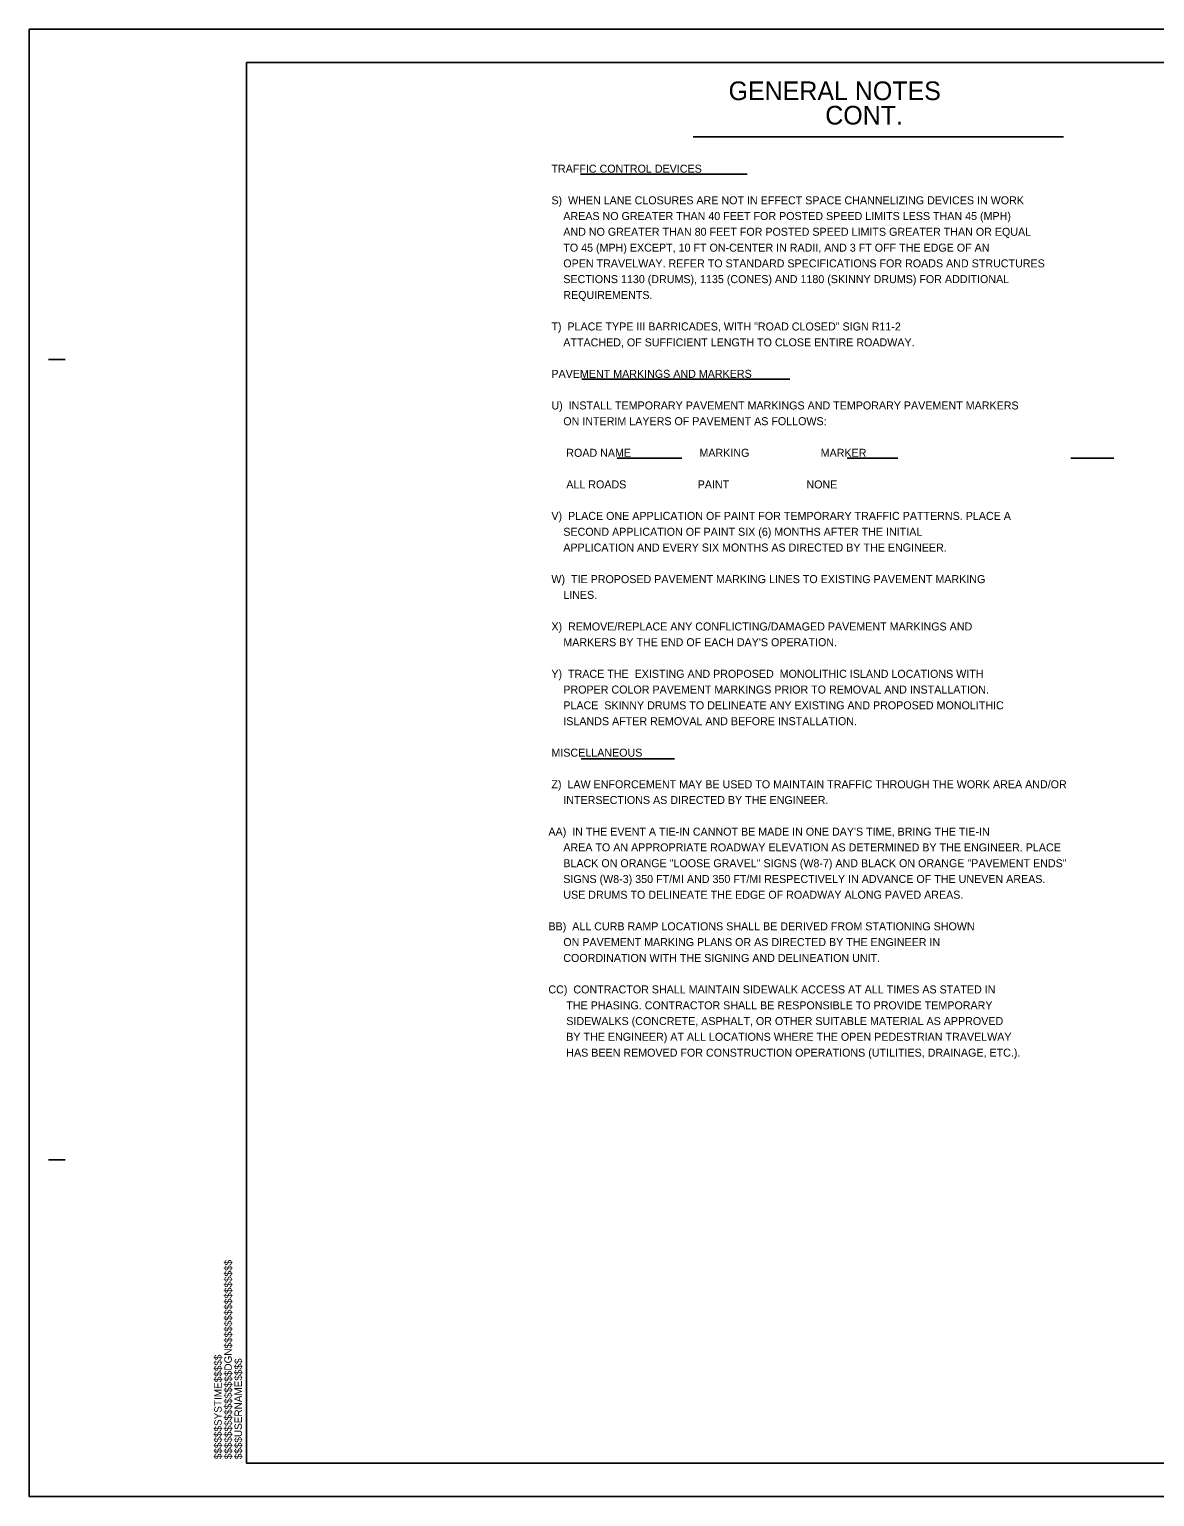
# Model space of a CAD drawing. Extents: x 762655 to 770567, y 650864 to 655190.
# Drawn here: x 764521 to 765365, y 652779 to 653879 of the extents above; entities that cross this region are included whole.
import ezdxf

# ---------------------------------------------------------------- set-up
doc = ezdxf.new("R2010")
doc.units = 0
for name, color, linetype in [('Default', 7, 'Continuous'), ('DEV BORDER CELL', 7, 'Continuous'), ('DEV TRANSPORTATION OPERATIONS PLAN SHEET', 7, 'Continuous'), ('Scratch_Level_3', 7, 'Continuous'), ('Sheet Plot Border Outside CELL', 7, 'Continuous')]:
    doc.layers.add(name, color=color, linetype=linetype)

msp = doc.modelspace()

# ---------------------------------------------------------------- linework, layer by layer
at = {"layer": 'Default'}
for p, q in [((764934.2, 653770.2), (765059.2, 653770.2)), ((764935.2, 653616.4), (765091.2, 653616.4)), ((764961.6, 653557.2), (765010.3, 653557.2)), ((765134.3, 653557.2), (765172.2, 653557.2)), ((765301.9, 653557.2), (765334.3, 653557.2)), ((764934.6, 653332), (765004.7, 653332))]:
    msp.add_line(p, q, dxfattribs=at)
at = {"layer": 'DEV BORDER CELL'}
for p, q in [((764684.8, 653853.8), (764684.8, 653853.8)), ((765018.6, 653798.2), (765296.5, 653798.2)), ((764535.3, 653631.3), (764547.8, 653631.3)), ((764535.3, 653031.3), (764547.8, 653031.3)), ((764683.8, 652803.8), (764683.8, 652803.8))]:
    msp.add_line(p, q, dxfattribs=at)
msp.add_lwpolyline([(766183.8, 653853.8), (764683.8, 653853.8), (764683.8, 652803.8), (766183.8, 652803.8)], close=True, dxfattribs=at)
at = {"layer": 'Scratch_Level_3'}
msp.add_lwpolyline([(764520.8, 653878.8), (766208.8, 653878.8), (766208.8, 652778.8), (764520.8, 652778.8)], close=True, dxfattribs=at)
at = {"layer": 'Sheet Plot Border Outside CELL'}
msp.add_lwpolyline([(764520.8, 652778.8), (766208.8, 652778.8), (766208.8, 653878.8), (764520.8, 653878.8)], close=True, dxfattribs=at)

# ---------------------------------------------------------------- texts
at = {"layer": 'Default'}
for s, p in [('       TRAFFIC CONTROL DEVICES', (764896.8, 653771.3)), ('       S)  WHEN LANE CLOSURES ARE NOT IN EFFECT SPACE CHANNELIZING DEVICES IN WORK', (764896.8, 653747.6)), ('           AREAS NO GREATER THAN 40 FEET FOR POSTED SPEED LIMITS LESS THAN 45 (MPH)', (764896.8, 653735.8)), ('           AND NO GREATER THAN 80 FEET FOR POSTED SPEED LIMITS GREATER THAN OR EQUAL', (764896.8, 653724)), ('           TO 45 (MPH) EXCEPT, 10 FT ON-CENTER IN RADII, AND 3 FT OFF THE EDGE OF AN ', (764896.8, 653712.1)), ('           OPEN TRAVELWAY. REFER TO STANDARD SPECIFICATIONS FOR ROADS AND STRUCTURES ', (764896.8, 653700.3)), ('           SECTIONS 1130 (DRUMS), 1135 (CONES) AND 1180 (SKINNY DRUMS) FOR ADDITIONAL', (764896.8, 653688.5)), ('           REQUIREMENTS.', (764896.8, 653676.6)), ('       T)  PLACE TYPE III BARRICADES, WITH "ROAD CLOSED" SIGN R11-2', (764896.8, 653653)), ('           ATTACHED, OF SUFFICIENT LENGTH TO CLOSE ENTIRE ROADWAY. ', (764896.8, 653641.1)), ('       PAVEMENT MARKINGS AND MARKERS', (764896.8, 653617.5)), ('       U)  INSTALL TEMPORARY PAVEMENT MARKINGS AND TEMPORARY PAVEMENT MARKERS', (764896.8, 653593.8)), ('           ON INTERIM LAYERS OF PAVEMENT AS FOLLOWS:', (764896.8, 653582)), ('            ROAD NAME                       MARKING                        MARKER', (764896.8, 653558.3)), ('            ALL ROADS                        PAINT                          NONE', (764896.8, 653534.6)), ('       V)  PLACE ONE APPLICATION OF PAINT FOR TEMPORARY TRAFFIC PATTERNS. PLACE A', (764896.8, 653511)), ('           SECOND APPLICATION OF PAINT SIX (6) MONTHS AFTER THE INITIAL', (764896.8, 653499.1)), ('           APPLICATION AND EVERY SIX MONTHS AS DIRECTED BY THE ENGINEER.', (764896.8, 653487.3)), ('       W)  TIE PROPOSED PAVEMENT MARKING LINES TO EXISTING PAVEMENT MARKING', (764896.8, 653463.6)), ('           LINES.', (764896.8, 653451.8)), ('       X)  REMOVE/REPLACE ANY CONFLICTING/DAMAGED PAVEMENT MARKINGS AND   ', (764896.8, 653428.1)), ("           MARKERS BY THE END OF EACH DAY'S OPERATION.", (764896.8, 653416.3)), ('       Y)  TRACE THE  EXISTING AND PROPOSED  MONOLITHIC ISLAND LOCATIONS WITH ', (764896.8, 653392.6)), ('           PROPER COLOR PAVEMENT MARKINGS PRIOR TO REMOVAL AND INSTALLATION.', (764896.8, 653380.8)), ('           PLACE  SKINNY DRUMS TO DELINEATE ANY EXISTING AND PROPOSED MONOLITHIC ', (764896.8, 653369)), ('           ISLANDS AFTER REMOVAL AND BEFORE INSTALLATION.', (764896.8, 653357.1)), ('       MISCELLANEOUS', (764896.8, 653333.5)), ('       Z)  LAW ENFORCEMENT MAY BE USED TO MAINTAIN TRAFFIC THROUGH THE WORK AREA AND/OR', (764896.8, 653309.8)), ('           INTERSECTIONS AS DIRECTED BY THE ENGINEER.', (764896.8, 653298)), ("      AA)  IN THE EVENT A TIE-IN CANNOT BE MADE IN ONE DAY'S TIME, BRING THE TIE-IN", (764896.8, 653274.3)), ('           AREA TO AN APPROPRIATE ROADWAY ELEVATION AS DETERMINED BY THE ENGINEER. PLACE', (764896.8, 653262.5)), ('           BLACK ON ORANGE "LOOSE GRAVEL" SIGNS (W8-7) AND BLACK ON ORANGE "PAVEMENT ENDS"', (764896.8, 653250.6)), ('           SIGNS (W8-3) 350 FT/MI AND 350 FT/MI RESPECTIVELY IN ADVANCE OF THE UNEVEN AREAS.', (764896.8, 653238.8)), ('           USE DRUMS TO DELINEATE THE EDGE OF ROADWAY ALONG PAVED AREAS.   ', (764896.8, 653227)), ('      BB)  ALL CURB RAMP LOCATIONS SHALL BE DERIVED FROM STATIONING SHOWN', (764896.8, 653203.3)), ('           ON PAVEMENT MARKING PLANS OR AS DIRECTED BY THE ENGINEER IN', (764896.8, 653191.5)), ('           COORDINATION WITH THE SIGNING AND DELINEATION UNIT.', (764896.8, 653179.6)), ('      CC)  CONTRACTOR SHALL MAINTAIN SIDEWALK ACCESS AT ALL TIMES AS STATED IN', (764896.8, 653156)), ('            THE PHASING. CONTRACTOR SHALL BE RESPONSIBLE TO PROVIDE TEMPORARY', (764896.8, 653144.1)), ('            SIDEWALKS (CONCRETE, ASPHALT, OR OTHER SUITABLE MATERIAL AS APPROVED', (764896.8, 653132.3)), ('            BY THE ENGINEER) AT ALL LOCATIONS WHERE THE OPEN PEDESTRIAN TRAVELWAY', (764896.8, 653120.5)), ('            HAS BEEN REMOVED FOR CONSTRUCTION OPERATIONS (UTILITIES, DRAINAGE, ETC.).', (764896.8, 653108.6))]:
    msp.add_text(s, height=6, dxfattribs=at).set_placement(p)
at = {"layer": 'DEV BORDER CELL'}
for s, p in [('$$$$$$$$$$$$$$$$DGN$$$$$$$$$$$$$$$$', (764672.7, 652806.8)), ('$$$$$$SYSTIME$$$$$', (764665.1, 652806.8)), ('$$$$USERNAME$$$$', (764680.3, 652806.8))]:
    msp.add_text(s, height=5.584, rotation=90, dxfattribs=at).set_placement(p)
at = {"layer": 'DEV TRANSPORTATION OPERATIONS PLAN SHEET'}
for s, p in [('GENERAL NOTES ', (765045.3, 653825.7)), ('CONT.', (765117.8, 653807.4))]:
    msp.add_text(s, height=14, dxfattribs=at).set_placement(p)

doc.saveas('drawing.dxf')
